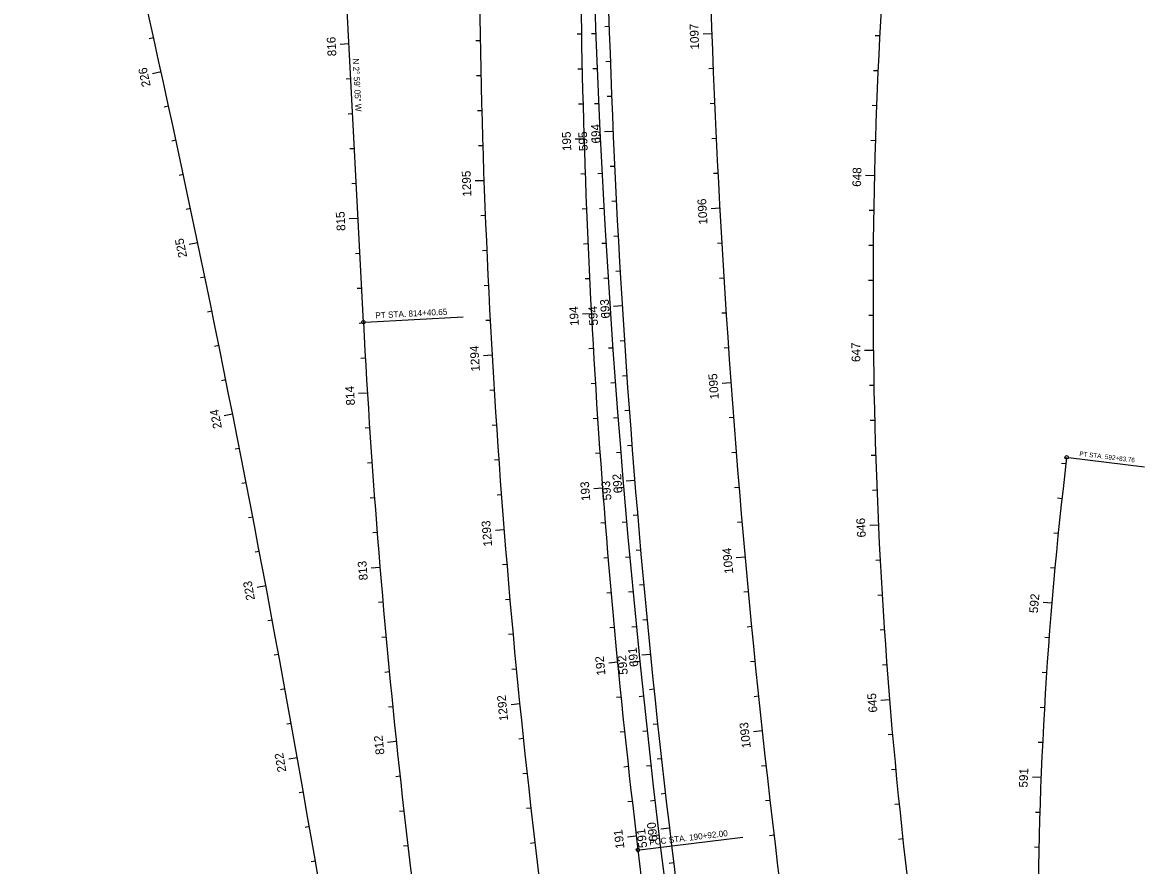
# Model space of a CAD drawing. Extents: x 919452 to 931278, y 583254 to 665650.
# Drawn here: x 928661 to 929303, y 634933 to 635415 of the extents above; entities that cross this region are included whole.
import ezdxf

# ---------------------------------------------------------------- set-up
doc = ezdxf.new("R2010")
doc.units = 0
for name, color, linetype in [('LaneLine', 7, 'Continuous'), ('PMStripe24W', 7, 'Continuous'), ('Scratch1_dp', 7, 'Continuous'), ('ScratchEle_dp', 7, 'Continuous'), ('ShldrHatch', 7, 'Continuous'), ('TollReader', 7, 'Continuous')]:
    doc.layers.add(name, color=color, linetype=linetype)

msp = doc.modelspace()

# ---------------------------------------------------------------- linework, layer by layer
at = {"layer": 'LaneLine'}
for p, q in [((928857.53, 635243.78), (928913.68, 635246.71)), ((929259.84, 635166.23), (929303.41, 635160.98)), ((929014.58, 634941.9), (929073.69, 634949.04))]:
    msp.add_line(p, q, dxfattribs=at)
for centre in [(928856.53, 635243.73), (929258.84, 635166.35), (929013.58, 634941.78)]:
    msp.add_circle(centre, 1, dxfattribs=at)
at = {"layer": 'Scratch1_dp'}
for p, q in [((928997.12, 635412.78), (928994.63, 635412.7)), ((928736.51, 635406.39), (928734.07, 635405.85)), ((928923.33, 635404.62), (928920.83, 635404.57)), ((928981.27, 635408.46), (928978.77, 635408.42)), ((928989.46, 635408.66), (928986.96, 635408.56)), ((929151.85, 635407.44), (929149.35, 635407.56)), ((928997.8, 635392.79), (928995.3, 635392.7)), ((928981.67, 635388.46), (928979.17, 635388.41)), ((928990.27, 635388.67), (928987.77, 635388.57)), ((929056.59, 635388.74), (929054.1, 635388.64)), ((929150.89, 635387.46), (929148.4, 635387.57)), ((928849.27, 635382.89), (928846.78, 635382.76)), ((928923.74, 635384.62), (928921.24, 635384.57)), ((928998.55, 635372.81), (928996.05, 635372.71)), ((928745.09, 635367.32), (928742.65, 635366.79)), ((928982.16, 635368.47), (928979.67, 635368.4)), ((928991.15, 635368.69), (928988.65, 635368.58)), ((929057.44, 635368.76), (929054.94, 635368.65)), ((929150.08, 635367.48), (929147.58, 635367.57)), ((928850.31, 635362.92), (928847.82, 635362.79)), ((928924.25, 635364.63), (928921.75, 635364.56)), ((928749.32, 635347.77), (928746.88, 635347.25)), ((929058.36, 635348.78), (929055.86, 635348.66)), ((929149.4, 635347.49), (929146.9, 635347.56)), ((928851.36, 635342.94), (928848.86, 635342.81)), ((928924.84, 635344.64), (928922.34, 635344.56)), ((928753.51, 635328.22), (928751.07, 635327.7)), ((928983.41, 635328.49), (928980.91, 635328.4)), ((928993.11, 635328.74), (928990.61, 635328.61)), ((929000.27, 635332.84), (928997.78, 635332.73)), ((929059.35, 635328.8), (929056.85, 635328.68)), ((928852.4, 635322.97), (928849.9, 635322.84)), ((928757.66, 635308.65), (928755.22, 635308.14)), ((928984.17, 635308.5), (928981.67, 635308.4)), ((928994.2, 635308.77), (928991.7, 635308.63)), ((929001.25, 635312.87), (928998.75, 635312.74)), ((928926.28, 635304.66), (928923.78, 635304.56)), ((929148.46, 635307.5), (929145.96, 635307.54)), ((928985.01, 635288.52), (928982.51, 635288.41)), ((928995.35, 635288.8), (928992.86, 635288.65)), ((929002.3, 635292.89), (928999.8, 635292.76)), ((929061.54, 635288.86), (929059.04, 635288.72)), ((928854.48, 635283.02), (928851.98, 635282.89)), ((928927.12, 635284.68), (928924.63, 635284.57)), ((929148.2, 635287.5), (929145.7, 635287.52)), ((928765.85, 635269.5), (928763.4, 635268.99)), ((929003.42, 635272.93), (929000.93, 635272.78)), ((928855.52, 635263.05), (928853.02, 635262.92)), ((928928.06, 635264.7), (928925.56, 635264.58)), ((928985.94, 635268.54), (928983.44, 635268.42)), ((928996.58, 635268.84), (928994.09, 635268.68)), ((929062.73, 635268.9), (929060.24, 635268.75)), ((929148.08, 635267.5), (929145.58, 635267.51)), ((928769.88, 635249.91), (928767.43, 635249.41)), ((928929.08, 635244.73), (928926.58, 635244.6)), ((929064, 635248.94), (929061.51, 635248.78)), ((929148.1, 635247.5), (929145.6, 635247.49)), ((928856.56, 635243.08), (928854.07, 635242.95)), ((929005.9, 635233), (929003.4, 635232.84)), ((928773.87, 635230.31), (928771.42, 635229.82)), ((928988.06, 635228.6), (928985.56, 635228.46)), ((928999.24, 635228.93), (928996.75, 635228.75)), ((929065.34, 635228.99), (929062.85, 635228.81)), ((928857.65, 635223.11), (928855.15, 635222.97)), ((929007.25, 635213.05), (929004.76, 635212.88)), ((928777.83, 635210.71), (928775.38, 635210.22)), ((928989.25, 635208.64), (928986.75, 635208.48)), ((929000.68, 635208.98), (928998.18, 635208.8)), ((929148.56, 635207.5), (929146.06, 635207.46)), ((928931.38, 635204.8), (928928.88, 635204.64)), ((929008.68, 635193.1), (929006.18, 635192.92)), ((928990.53, 635188.68), (928988.03, 635188.51)), ((929002.18, 635189.04), (928999.69, 635188.85)), ((929068.23, 635189.09), (929065.74, 635188.9)), ((929149, 635187.51), (929146.5, 635187.44)), ((928860.09, 635183.18), (928857.59, 635183.02)), ((928932.65, 635184.84), (928930.16, 635184.67)), ((929010.18, 635173.16), (929007.68, 635172.96)), ((928785.62, 635171.47), (928783.17, 635170.99)), ((928991.89, 635168.72), (928989.4, 635168.55)), ((929003.76, 635169.1), (929001.27, 635168.9)), ((929069.78, 635169.15), (929067.28, 635168.95)), ((929149.58, 635167.52), (929147.08, 635167.44)), ((928861.44, 635163.23), (928858.94, 635163.05)), ((928934.02, 635164.88), (928931.52, 635164.71)), ((929258.4, 635162.61), (929255.91, 635162.91)), ((928789.45, 635151.84), (928787, 635151.37)), ((929071.39, 635149.22), (929068.9, 635149.01)), ((929150.3, 635147.53), (929147.8, 635147.43)), ((928862.87, 635143.28), (928860.38, 635143.09)), ((928935.47, 635144.94), (928932.97, 635144.75)), ((929256.12, 635142.74), (929253.64, 635143.02)), ((928793.25, 635132.21), (928790.8, 635131.74)), ((928994.88, 635128.84), (928992.39, 635128.64)), ((929007.12, 635129.24), (929004.63, 635129.02)), ((929013.4, 635133.29), (929010.91, 635133.08)), ((929073.08, 635129.29), (929070.59, 635129.07)), ((928864.4, 635123.34), (928861.9, 635123.14)), ((929254.02, 635122.85), (929251.54, 635123.1)), ((928797.01, 635112.56), (928794.55, 635112.1)), ((928996.5, 635108.9), (928994.01, 635108.69)), ((929008.9, 635109.32), (929006.41, 635109.09)), ((929015.13, 635113.36), (929012.64, 635113.14)), ((928938.62, 635105.06), (928936.13, 635104.85)), ((929152.15, 635107.57), (929149.65, 635107.44)), ((929252.1, 635102.95), (929249.61, 635103.18)), ((929016.93, 635093.44), (929014.44, 635093.21)), ((928867.7, 635083.47), (928865.21, 635083.26)), ((928940.33, 635085.13), (928937.84, 635084.92)), ((928998.22, 635088.97), (928995.73, 635088.76)), ((929010.75, 635089.41), (929008.26, 635089.17)), ((929076.67, 635089.45), (929074.18, 635089.22)), ((929153.28, 635087.61), (929150.79, 635087.45)), ((928804.4, 635073.25), (928801.95, 635072.8)), ((929018.8, 635073.53), (929016.31, 635073.29)), ((928942.12, 635065.21), (928939.63, 635064.98)), ((929000.02, 635069.06), (928997.53, 635068.83)), ((929012.67, 635069.5), (929010.19, 635069.25)), ((929078.56, 635069.54), (929076.08, 635069.3)), ((929154.56, 635067.65), (929152.07, 635067.48)), ((928869.49, 635063.55), (928867, 635063.33)), ((929248.77, 635063.09), (929246.28, 635063.27)), ((928808.04, 635053.59), (928805.58, 635053.14)), ((928944, 635045.3), (928941.51, 635045.06)), ((929080.53, 635049.64), (929078.04, 635049.38)), ((929155.97, 635047.7), (929153.48, 635047.51)), ((928871.36, 635043.64), (928868.87, 635043.4)), ((929247.37, 635043.13), (929244.87, 635043.3)), ((928811.64, 635033.91), (928809.18, 635033.47)), ((929022.78, 635033.73), (929020.29, 635033.47)), ((929003.87, 635029.24), (929001.39, 635028.99)), ((929016.73, 635029.71), (929014.24, 635029.44)), ((929082.57, 635029.74), (929080.08, 635029.48)), ((928873.32, 635023.74), (928870.83, 635023.49)), ((929246.14, 635023.17), (929243.64, 635023.32)), ((928815.2, 635014.23), (928812.74, 635013.79)), ((929024.88, 635013.84), (929022.39, 635013.57)), ((929005.93, 635009.35), (929003.45, 635009.09)), ((929018.86, 635009.82), (929016.37, 635009.55)), ((929159.22, 635007.83), (929156.73, 635007.61)), ((928948.02, 635005.51), (928945.53, 635005.24)), ((929245.08, 635003.2), (929242.59, 635003.32)), ((929027.05, 634993.96), (929024.57, 634993.68)), ((929008.08, 634989.46), (929005.6, 634989.19)), ((929021.06, 634989.94), (929018.57, 634989.66)), ((929086.85, 634989.97), (929084.37, 634989.69)), ((929161.05, 634987.91), (929158.56, 634987.67)), ((928877.49, 634983.96), (928875.01, 634983.69)), ((928950.15, 634985.62), (928947.67, 634985.35)), ((928822.2, 634974.85), (928819.74, 634974.42)), ((929029.3, 634974.08), (929026.82, 634973.8)), ((929010.31, 634969.59), (929007.83, 634969.3)), ((929023.33, 634970.07), (929020.84, 634969.78)), ((929089.1, 634970.1), (929086.61, 634969.81)), ((929163.02, 634968.01), (929160.54, 634967.75)), ((928879.71, 634964.08), (928877.23, 634963.8)), ((928952.38, 634965.74), (928949.89, 634965.46)), ((929243.5, 634963.23), (929241, 634963.31)), ((928825.64, 634955.15), (928823.18, 634954.72)), ((929091.41, 634950.23), (929088.93, 634949.94)), ((928882.01, 634944.21), (928879.53, 634943.92)), ((928954.68, 634945.88), (928952.2, 634945.58)), ((929165.13, 634948.12), (929162.65, 634947.85)), ((929242.97, 634943.24), (929240.47, 634943.3)), ((928829.04, 634935.44), (928826.58, 634935.02)), ((929034.02, 634934.36), (929031.54, 634934.06))]:
    msp.add_line(p, q, dxfattribs=at)
at = {"layer": 'ScratchEle_dp'}
msp.add_line((928856.53, 635243.73), (928842.76, 635507.87), dxfattribs=at)
for centre, radius, start, end in [((934714.76, 635630.15), 5729.58, 175.955434, 198.89818), ((919023.27, 633253.37), 9949, 9.590734, 14.358327), ((934757.45, 635620.79), 5705.58, 180.06217, 188.19915), ((934313.46, 635582.15), 5319.04, 180.05369, 188.30596), ((932014.36, 635260.36), 2866.29, 174.76849, 187.10964), ((933567.21, 635491.59), 4644.7, 180.06217, 187.81416), ((933567.17, 635491.59), 4586.66, 180.05369, 186.8847), ((933433.97, 635482.4), 4583.66, 182.98469, 189.59073), ((931534.4, 634892.3), 2292, 173.13281, 187.58667), ((934714.76, 635630.15), 5742.58, 186.884702, 191.983164)]:
    msp.add_arc(centre, radius, start, end, dxfattribs=at)
at = {"layer": 'TollReader'}
for p, q in [((929055.81, 635408.73), (929050.82, 635408.54)), ((928848.23, 635402.86), (928843.24, 635402.6)), ((928740.82, 635386.86), (928735.94, 635385.79)), ((928999.37, 635352.82), (928994.38, 635352.61)), ((928982.75, 635348.48), (928977.75, 635348.32)), ((928992.09, 635348.71), (928987.1, 635348.47)), ((929148.86, 635327.49), (929143.86, 635327.61)), ((928925.51, 635324.65), (928920.52, 635324.47)), ((929060.41, 635308.83), (929055.41, 635308.56)), ((928853.44, 635303), (928848.44, 635302.74)), ((928761.77, 635289.08), (928756.88, 635288.06)), ((929004.62, 635252.96), (928999.63, 635252.65)), ((928986.95, 635248.57), (928981.96, 635248.3)), ((928997.88, 635248.88), (928992.89, 635248.55)), ((928930.18, 635224.76), (928925.19, 635224.47)), ((929148.26, 635227.5), (929143.26, 635227.44)), ((929066.75, 635209.04), (929061.76, 635208.67)), ((928858.82, 635203.14), (928853.83, 635202.84)), ((928781.74, 635191.09), (928776.84, 635190.12)), ((928993.34, 635148.78), (928988.36, 635148.4)), ((929005.4, 635149.17), (929000.42, 635148.75)), ((929011.75, 635153.22), (929006.77, 635152.81)), ((928937, 635124.99), (928932.02, 635124.6)), ((929151.15, 635127.55), (929146.16, 635127.32)), ((929074.84, 635109.36), (929069.86, 635108.92)), ((928866.01, 635103.4), (928861.02, 635102.99)), ((928800.73, 635092.91), (928795.81, 635091.99)), ((929250.35, 635083.02), (929245.37, 635083.44)), ((929020.75, 635053.63), (929015.78, 635053.13)), ((929001.9, 635049.14), (928996.93, 635048.66)), ((929014.67, 635049.6), (929009.69, 635049.09)), ((928945.97, 635025.4), (928940.99, 635024.9)), ((929157.53, 635027.76), (929152.54, 635027.35)), ((929084.68, 635009.85), (929079.7, 635009.31)), ((928875.36, 635003.84), (928870.39, 635003.32)), ((928818.72, 634994.55), (928813.8, 634993.67)), ((929244.2, 634983.22), (929239.21, 634983.42)), ((929012.63, 634949.72), (929007.67, 634949.13)), ((929025.67, 634950.21), (929020.7, 634949.61)), ((929031.62, 634954.22), (929026.66, 634953.63))]:
    msp.add_line(p, q, dxfattribs=at)

# ---------------------------------------------------------------- texts
at = {"layer": 'LaneLine'}
for s, height, rotation, p in [('PT STA. 814+40.65', 3.5, 2.98469, (928863.43, 635245.84)), ('PT STA. 592+83.76', 2.625, 353.13281, (929266, 635167.25)), ('PCC STA. 190+92.00', 3.5, 6.8847, (929020.32, 634944.36))]:
    msp.add_text(s, height=height, rotation=rotation, dxfattribs=at).set_placement(p)
at = {"layer": 'PMStripe24W'}
msp.add_text('N 2%%d 59\' 05" W', height=3.5, rotation=272.98469, dxfattribs=at).set_placement((928850.42, 635394.49))
at = {"layer": 'ShldrHatch'}
for s, rotation, p in [('1097', 92.13005, (929048.64, 635399.74)), ('816', 92.98469, (928841.08, 635395.95)), ('226', 102.38281, (928734.9, 635378.87)), ('694', 92.47107, (928992.16, 635346.02)), ('195', 91.78802, (928975.45, 635341.68)), ('595', 92.81552, (928984.93, 635341.79)), ('1295', 92.05982, (928918.33, 635315.58)), ('648', 88.6579, (929141.21, 635321.1)), ('1096', 93.13425, (929053.4, 635299.66)), ('815', 92.98469, (928846.29, 635296.05)), ('225', 101.80691, (928755.78, 635281.12)), ('693', 93.54825, (928997.55, 635245.92)), ('194', 93.0372, (928979.81, 635241.69)), ('594', 93.81552, (928990.83, 635241.91)), ('647', 90.65685, (929140.84, 635220.94)), ('1294', 93.2934, (928923.2, 635215.61)), ('1095', 94.13846, (929059.9, 635199.71)), ('814', 93.49286, (928851.73, 635196.21)), ('224', 101.23102, (928775.65, 635183.27)), ('692', 94.62543, (929004.81, 635146.05)), ('193', 94.28638, (928986.35, 635141.64)), ('593', 94.81552, (928998.48, 635141.97)), ('1293', 94.52697, (928930.22, 635115.6)), ('646', 92.65581, (929143.96, 635120.67)), ('1094', 95.14266, (929068.15, 635100)), ('813', 94.74286, (928859.08, 635096.22)), ('223', 100.65512, (928794.57, 635085.05)), ('592', 85.22675, (929242.33, 635077.08)), ('691', 95.70262, (929013.9, 635046.77)), ('192', 95.53556, (928995.07, 635041.87)), ('592', 95.81552, (929007.87, 635042.29)), ('1292', 95.76054, (928939.39, 635015.86)), ('645', 94.65476, (929150.59, 635020.6)), ('1093', 96.14687, (929078.16, 635000.26)), ('812', 95.99286, (928868.59, 634996.51)), ('222', 100.07923, (928812.49, 634986.75)), ('591', 87.72657, (929236.47, 634977.39)), ('690', 96.7798, (929024.95, 634946.86)), ('191', 96.78475, (929005.91, 634942.75)), ('591', 96.81552, (929018.95, 634943.22))]:
    msp.add_text(s, height=5, rotation=rotation, dxfattribs=at).set_placement(p)

doc.saveas('drawing.dxf')
